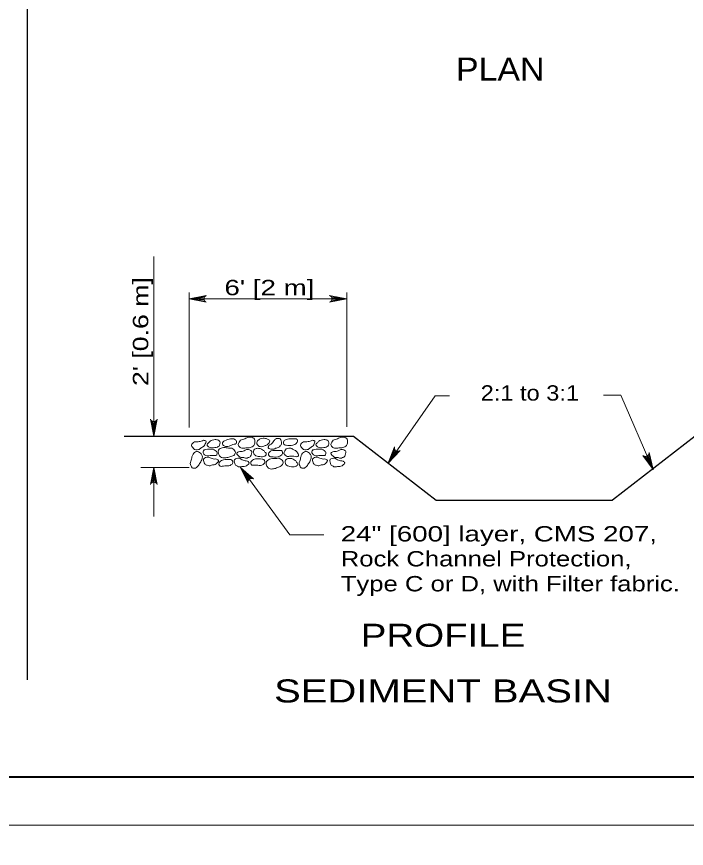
# Model space of a CAD drawing. Extents: x 1043.1 to 1101.1, y 672.4 to 716.4.
# Drawn here: x 1065.65 to 1072.63, y 694.15 to 702.82 of the extents above; entities that cross this region are included whole.
import ezdxf
from ezdxf.enums import TextEntityAlignment as Align

# ---------------------------------------------------------------- set-up
doc = ezdxf.new("R2010")
doc.units = 0
doc.header["$LTSCALE"] = 0.064
doc.linetypes.add('LONG_DASHED', pattern=[7.5, 6, -1.5])
doc.layers.add('1', color=7, linetype='Continuous', lineweight=13)

msp = doc.modelspace()

# ---------------------------------------------------------------- linework, layer by layer
at = {"layer": '1', "lineweight": 25}
for p, q in [((1065.75725, 705.79967), (1065.75725, 695.90875)), ((1066.76875, 698.44833), (1069.16058, 698.44833)), ((1072.72475, 698.44833), (1071.86283, 697.78133))]:
    msp.add_line(p, q, dxfattribs=at)
at = {"layer": '1'}
for p, q in [((1067.07925, 700.32167), (1067.07925, 698.44833)), ((1067.44858, 699.94717), (1067.44858, 698.53933)), ((1069.09117, 699.94717), (1069.09117, 698.54667)), ((1067.61175, 699.90575), (1067.44858, 699.88083)), ((1067.60558, 699.89533), (1067.44858, 699.88083)), ((1069.09117, 699.88083), (1067.44858, 699.88083)), ((1067.60275, 699.88083), (1067.44858, 699.88083)), ((1067.60442, 699.86942), (1067.44858, 699.88083)), ((1067.60983, 699.85825), (1067.44858, 699.88083)), ((1067.59725, 699.88083), (1067.45083, 699.88083)), ((1068.928, 699.85592), (1069.09117, 699.88083)), ((1068.92992, 699.90342), (1069.09117, 699.88083)), ((1068.93417, 699.86633), (1069.09117, 699.88083)), ((1068.93533, 699.89225), (1069.09117, 699.88083)), ((1068.937, 699.88083), (1069.09117, 699.88083)), ((1068.9425, 699.88083), (1069.08892, 699.88083)), ((1067.05433, 698.6115), (1067.07925, 698.44833)), ((1067.06475, 698.60533), (1067.07925, 698.44833)), ((1067.10183, 698.60958), (1067.07925, 698.44833)), ((1067.09067, 698.60417), (1067.07925, 698.44833)), ((1067.07925, 698.6025), (1067.07925, 698.44833)), ((1067.07925, 698.597), (1067.07925, 698.45058)), ((1069.58933, 698.31933), (1069.52217, 698.1685)), ((1069.59483, 698.30842), (1069.52217, 698.1685)), ((1069.60542, 698.29825), (1069.52217, 698.1685)), ((1069.61592, 698.2935), (1069.52217, 698.1685)), ((1069.62825, 698.292), (1069.52217, 698.1685)), ((1069.6025, 698.29358), (1069.52333, 698.17042)), ((1072.196, 698.24008), (1072.28517, 698.10117)), ((1072.208, 698.23867), (1072.28517, 698.10117)), ((1072.22242, 698.24192), (1072.28517, 698.10117)), ((1072.22467, 698.237), (1072.28433, 698.10317)), ((1072.23217, 698.24808), (1072.28517, 698.10117)), ((1072.24017, 698.25767), (1072.28517, 698.10117)), ((1067.44858, 698.12408), (1066.94558, 698.12408)), ((1067.05667, 697.96283), (1067.07925, 698.12408)), ((1067.06783, 697.96825), (1067.07925, 698.12408)), ((1067.07925, 697.61308), (1067.07925, 698.12408)), ((1067.07925, 697.96992), (1067.07925, 698.12408)), ((1067.09375, 697.96708), (1067.07925, 698.12408)), ((1067.10417, 697.96092), (1067.07925, 698.12408)), ((1067.07925, 697.97542), (1067.07925, 698.12183)), ((1068.07558, 698.00092), (1067.98217, 698.1235)), ((1068.08883, 698.00742), (1067.98217, 698.1235)), ((1068.10092, 698.00883), (1067.98217, 698.1235)), ((1068.06775, 697.99258), (1067.98217, 698.1235)), ((1068.06208, 697.98158), (1067.98217, 698.1235)), ((1068.07225, 698.00525), (1067.98358, 698.12175))]:
    msp.add_line(p, q, dxfattribs=at)
at = {"layer": '1', "linetype": 'LONG_DASHED'}
for points in [[(1043.14425, 694.39508), (1077.14425, 694.39508), (1077.14425, 716.39508), (1043.14425, 716.39508)], [(1043.14425, 672.39508), (1077.14425, 672.39508), (1077.14425, 694.39508), (1043.14425, 694.39508)]]:
    msp.add_lwpolyline(points, close=True, dxfattribs=at)
at = {"layer": '1', "lineweight": 25}
for points in [[(1076.64425, 694.89508), (1045.14425, 694.89508), (1045.14425, 715.89508)], [(1069.16058, 698.44833), (1070.0225, 697.78133), (1071.86283, 697.78133)]]:
    msp.add_lwpolyline(points, dxfattribs=at)
at = {"layer": '1', "lineweight": 40}
msp.add_lwpolyline([(1045.14425, 715.89508), (1076.64425, 715.89508), (1076.64425, 694.89508), (1045.14425, 694.89508)], close=True, dxfattribs=at)
msp.add_lwpolyline([(1076.64425, 694.89508), (1045.14425, 694.89508), (1045.14425, 715.89508)], dxfattribs=at)
at = {"layer": '1'}
for points in [[(1067.62675, 699.91642), (1067.44858, 699.88083), (1067.62675, 699.84525)], [(1068.91308, 699.84525), (1069.09117, 699.88083), (1068.91308, 699.91642)], [(1070.16233, 698.871), (1070.013, 698.871), (1069.52217, 698.1685)], [(1071.7705, 698.87883), (1071.95125, 698.87883), (1072.28742, 698.10025)], [(1067.04358, 698.6265), (1067.07925, 698.44833), (1067.11492, 698.6265)], [(1069.58842, 698.33767), (1069.52217, 698.1685), (1069.64833, 698.29917)], [(1072.18008, 698.24942), (1072.28517, 698.10117), (1072.24525, 698.27842)], [(1067.11492, 697.946), (1067.07925, 698.12408), (1067.04358, 697.946)], [(1068.11833, 698.00342), (1067.98217, 698.1235), (1068.06183, 697.96033)], [(1068.85283, 697.42283), (1068.49617, 697.42283), (1067.9835, 698.12525)]]:
    msp.add_lwpolyline(points, dxfattribs=at)
for centre, start, end in [((1067.64109, 699.88079), 112.08605, 247.91218), ((1068.89866, 699.88087), 292.08605, 67.91218), ((1067.07929, 698.64084), 202.08605, 337.91218), ((1069.62619, 698.33048), 169.38859, 305.21471), ((1072.20684, 698.27705), 226.10574, 1.93187), ((1067.07921, 697.93158), 22.08605, 157.91218), ((1068.09888, 697.97042), 59.38859, 195.21471)]:
    msp.add_arc(centre, 0.03845, start, end, dxfattribs=at)
for points in [[(1067.61217, 698.35908), (1067.62058, 698.37867), (1067.62142, 698.4), (1067.61167, 698.40425), (1067.59767, 698.40683), (1067.57408, 698.39667), (1067.55275, 698.39308), (1067.52908, 698.39117), (1067.51242, 698.39242), (1067.49458, 698.38508), (1067.47683, 698.36533), (1067.472, 698.35133), (1067.48542, 698.331), (1067.50392, 698.31175), (1067.53267, 698.30875), (1067.55375, 698.312), (1067.58092, 698.333), (1067.59675, 698.34133), (1067.61217, 698.35908)], [(1067.75942, 698.34675), (1067.74183, 698.3355), (1067.71583, 698.33025), (1067.68492, 698.32925), (1067.65742, 698.33492), (1067.64275, 698.34642), (1067.63508, 698.36208), (1067.64475, 698.37542), (1067.66583, 698.397), (1067.68842, 698.40875), (1067.71908, 698.41433), (1067.75242, 698.40708), (1067.76683, 698.39308), (1067.76925, 698.3695), (1067.75942, 698.34675)], [(1067.86525, 698.34683), (1067.836, 698.34242), (1067.80617, 698.3525), (1067.79608, 698.37092), (1067.8015, 698.39092), (1067.8165, 698.40058), (1067.88, 698.42275), (1067.92492, 698.416), (1067.942, 698.39292), (1067.93633, 698.37225), (1067.91858, 698.3655), (1067.86525, 698.34683)], [(1068.10392, 698.33933), (1068.12225, 698.35392), (1068.13367, 698.38508), (1068.12192, 698.42767), (1068.07825, 698.4405), (1068.04892, 698.43333), (1068.00558, 698.41458), (1067.98358, 698.40683), (1067.969, 698.38708), (1067.95992, 698.36233), (1067.97833, 698.3325), (1067.99775, 698.326), (1068.04058, 698.32683), (1068.08492, 698.33225), (1068.10392, 698.33933)], [(1068.17875, 698.3435), (1068.1995, 698.34033), (1068.22533, 698.346), (1068.25408, 698.35758), (1068.27683, 698.37383), (1068.28558, 698.39042), (1068.28642, 698.40775), (1068.27208, 698.416), (1068.24408, 698.42717), (1068.21867, 698.42892), (1068.18842, 698.42142), (1068.16083, 698.4015), (1068.15325, 698.38267), (1068.16067, 698.36042), (1068.17875, 698.3435)], [(1068.31025, 698.31317), (1068.2895, 698.31792), (1068.27142, 698.32958), (1068.27383, 698.34008), (1068.27975, 698.35308), (1068.30175, 698.36633), (1068.31717, 698.3815), (1068.33225, 698.39975), (1068.34117, 698.414), (1068.35733, 698.42408), (1068.38383, 698.42717), (1068.398, 698.42283), (1068.40683, 698.40017), (1068.41167, 698.37408), (1068.39725, 698.34867), (1068.3825, 698.33358), (1068.34967, 698.32367), (1068.33367, 698.31558), (1068.31025, 698.31317)], [(1068.489, 698.42192), (1068.46008, 698.41642), (1068.43517, 698.39692), (1068.43175, 698.37617), (1068.44375, 698.35925), (1068.46092, 698.35492), (1068.528, 698.355), (1068.56817, 698.37617), (1068.57683, 698.40358), (1068.56475, 698.42125), (1068.54567, 698.42192), (1068.489, 698.42192)], [(1068.74767, 698.35908), (1068.75608, 698.37867), (1068.75692, 698.4), (1068.74717, 698.40425), (1068.73317, 698.40683), (1068.70958, 698.39667), (1068.68825, 698.39308), (1068.66458, 698.39117), (1068.64792, 698.39242), (1068.63008, 698.38508), (1068.61233, 698.36533), (1068.6075, 698.35133), (1068.62092, 698.331), (1068.63942, 698.31175), (1068.66817, 698.30875), (1068.68925, 698.312), (1068.71642, 698.333), (1068.73225, 698.34133), (1068.74767, 698.35908)], [(1068.89492, 698.34675), (1068.87733, 698.3355), (1068.85133, 698.33025), (1068.82042, 698.32925), (1068.79292, 698.33492), (1068.77825, 698.34642), (1068.77058, 698.36208), (1068.78025, 698.37542), (1068.80133, 698.397), (1068.82392, 698.40875), (1068.85458, 698.41433), (1068.88792, 698.40708), (1068.90233, 698.39308), (1068.90475, 698.3695), (1068.89492, 698.34675)], [(1069.07075, 698.33933), (1069.08908, 698.35392), (1069.1005, 698.38508), (1069.08875, 698.42767), (1069.04508, 698.4405), (1069.01575, 698.43333), (1068.97242, 698.41458), (1068.95042, 698.40683), (1068.93583, 698.38708), (1068.92675, 698.36233), (1068.94517, 698.3325), (1068.96458, 698.326), (1069.00742, 698.32683), (1069.05175, 698.33225), (1069.07075, 698.33933)], [(1067.58483, 698.2215), (1067.58425, 698.24492), (1067.56625, 698.27292), (1067.52508, 698.28908), (1067.48875, 698.26208), (1067.47692, 698.23433), (1067.4655, 698.18833), (1067.45858, 698.16592), (1067.46558, 698.14242), (1067.47983, 698.12042), (1067.51467, 698.11717), (1067.5315, 698.12875), (1067.55683, 698.1635), (1067.57917, 698.20217), (1067.58483, 698.2215)], [(1067.65217, 698.24533), (1067.62292, 698.24942), (1067.59708, 698.26767), (1067.59275, 698.28825), (1067.60375, 698.30583), (1067.62075, 698.31075), (1067.68792, 698.31392), (1067.72892, 698.2945), (1067.73892, 698.26767), (1067.7275, 698.2495), (1067.70858, 698.248), (1067.65217, 698.24533)], [(1067.79808, 698.22483), (1067.77633, 698.23333), (1067.75608, 698.25967), (1067.75458, 698.30392), (1067.79233, 698.329), (1067.82267, 698.33092), (1067.86967, 698.326), (1067.89308, 698.32492), (1067.91283, 698.3105), (1067.92867, 698.28975), (1067.92, 698.25567), (1067.90342, 698.24367), (1067.86242, 698.23167), (1067.81842, 698.22367), (1067.79808, 698.22483)], [(1067.96958, 698.23858), (1067.95375, 698.253), (1067.94408, 698.272), (1067.95117, 698.27983), (1067.96283, 698.28825), (1067.9885, 698.28883), (1068.00942, 698.29433), (1068.03158, 698.30267), (1068.04633, 698.31075), (1068.0655, 698.31158), (1068.09, 698.301), (1068.10008, 698.29025), (1068.09642, 698.26625), (1068.08767, 698.24092), (1068.06292, 698.22608), (1068.04242, 698.22033), (1068.009, 698.228), (1067.99108, 698.229), (1067.96958, 698.23858)], [(1068.12692, 698.25883), (1068.14367, 698.24608), (1068.169, 698.23875), (1068.19983, 698.23533), (1068.22775, 698.23883), (1068.24325, 698.24917), (1068.25225, 698.26425), (1068.24358, 698.27817), (1068.22425, 698.30133), (1068.20258, 698.31508), (1068.17242, 698.32283), (1068.13875, 698.31833), (1068.12317, 698.3055), (1068.11892, 698.28225), (1068.12692, 698.25883)], [(1068.33375, 698.30125), (1068.30467, 698.29575), (1068.27983, 698.27633), (1068.27633, 698.25558), (1068.28833, 698.23858), (1068.3055, 698.23442), (1068.37258, 698.2345), (1068.41283, 698.25558), (1068.42158, 698.283), (1068.40933, 698.30067), (1068.39042, 698.30125), (1068.33375, 698.30125)], [(1068.57375, 698.28417), (1068.5845, 698.26575), (1068.58808, 698.24475), (1068.57883, 698.23917), (1068.56525, 698.23483), (1068.54058, 698.24183), (1068.51908, 698.24292), (1068.49533, 698.24158), (1068.47892, 698.23833), (1068.4605, 698.24317), (1068.44042, 698.26067), (1068.43375, 698.27392), (1068.4445, 698.29567), (1068.46033, 698.31717), (1068.4885, 698.32392), (1068.50967, 698.32333), (1068.53933, 698.306), (1068.55608, 698.29975), (1068.57375, 698.28417)], [(1068.72033, 698.2215), (1068.71975, 698.24492), (1068.70175, 698.27292), (1068.66058, 698.28908), (1068.62425, 698.26208), (1068.61242, 698.23433), (1068.601, 698.18833), (1068.59408, 698.16592), (1068.60108, 698.14242), (1068.61533, 698.12042), (1068.65017, 698.11717), (1068.667, 698.12875), (1068.69233, 698.1635), (1068.71467, 698.20217), (1068.72033, 698.2215)], [(1068.78767, 698.24533), (1068.75842, 698.24942), (1068.73258, 698.26767), (1068.72825, 698.28825), (1068.73925, 698.30583), (1068.75625, 698.31075), (1068.82342, 698.31392), (1068.86442, 698.2945), (1068.87442, 698.26767), (1068.863, 698.2495), (1068.84408, 698.248), (1068.78767, 698.24533)], [(1068.95217, 698.23858), (1068.93633, 698.253), (1068.92667, 698.272), (1068.93375, 698.27983), (1068.94542, 698.28825), (1068.97108, 698.28883), (1068.992, 698.29433), (1069.01417, 698.30267), (1069.02892, 698.31075), (1069.04808, 698.31158), (1069.07258, 698.301), (1069.08267, 698.29025), (1069.079, 698.26625), (1069.07025, 698.24092), (1069.0455, 698.22608), (1069.025, 698.22033), (1068.99158, 698.228), (1068.97367, 698.229), (1068.95217, 698.23858)], [(1067.72942, 698.16142), (1067.74467, 698.17633), (1067.75383, 698.19558), (1067.7465, 698.20325), (1067.73467, 698.21125), (1067.70908, 698.21108), (1067.68792, 698.216), (1067.6655, 698.22358), (1067.65058, 698.231), (1067.63133, 698.23133), (1067.60733, 698.22008), (1067.59742, 698.209), (1067.60175, 698.18508), (1067.61125, 698.16017), (1067.63658, 698.14617), (1067.65725, 698.141), (1067.69042, 698.14958), (1067.70817, 698.15108), (1067.72942, 698.16142)], [(1067.84725, 698.139), (1067.87617, 698.14575), (1067.90008, 698.16633), (1067.90258, 698.18725), (1067.89008, 698.20375), (1067.87258, 698.20708), (1067.80525, 698.20392), (1067.76625, 698.181), (1067.75883, 698.15325), (1067.77175, 698.13625), (1067.79075, 698.13642), (1067.84725, 698.139)], [(1068.04525, 698.14108), (1068.06217, 698.15417), (1068.07342, 698.17217), (1068.067, 698.18067), (1068.05608, 698.18992), (1068.0305, 698.19258), (1068.01017, 698.19975), (1067.98858, 698.20975), (1067.97458, 698.21892), (1067.9555, 698.22133), (1067.93033, 698.21275), (1067.91917, 698.20283), (1067.921, 698.17858), (1067.92783, 698.15283), (1067.95133, 698.13592), (1067.97125, 698.12858), (1068.00525, 698.13358), (1068.02308, 698.13317), (1068.04525, 698.14108)], [(1068.17708, 698.14458), (1068.20625, 698.14883), (1068.232, 698.16725), (1068.23617, 698.18792), (1068.22508, 698.20533), (1068.20808, 698.21017), (1068.14075, 698.21275), (1068.09992, 698.19325), (1068.09008, 698.16625), (1068.10158, 698.14817), (1068.12058, 698.14683), (1068.17708, 698.14458)], [(1068.30533, 698.10725), (1068.28267, 698.11275), (1068.25908, 698.13625), (1068.25192, 698.17975), (1068.286, 698.20975), (1068.31558, 698.21567), (1068.36283, 698.217), (1068.38625, 698.21917), (1068.40767, 698.2075), (1068.42625, 698.18892), (1068.42208, 698.15392), (1068.40725, 698.13992), (1068.36808, 698.12258), (1068.32567, 698.10875), (1068.30533, 698.10725)], [(1068.45658, 698.15417), (1068.47333, 698.1415), (1068.49867, 698.13408), (1068.5295, 698.13067), (1068.55725, 698.13408), (1068.57283, 698.14442), (1068.58175, 698.15942), (1068.57308, 698.17342), (1068.55375, 698.19667), (1068.53217, 698.21033), (1068.50208, 698.21808), (1068.46842, 698.21358), (1068.45283, 698.20075), (1068.44858, 698.17758), (1068.45658, 698.15417)], [(1068.86492, 698.16142), (1068.88017, 698.17633), (1068.88933, 698.19558), (1068.882, 698.20325), (1068.87017, 698.21125), (1068.84458, 698.21108), (1068.82342, 698.216), (1068.801, 698.22358), (1068.78608, 698.231), (1068.76683, 698.23133), (1068.74283, 698.22008), (1068.73292, 698.209), (1068.73725, 698.18508), (1068.74675, 698.16017), (1068.77208, 698.14617), (1068.79275, 698.141), (1068.82592, 698.14958), (1068.84367, 698.15108), (1068.86492, 698.16142)], [(1069.04183, 698.14108), (1069.05875, 698.15417), (1069.07, 698.17217), (1069.06358, 698.18067), (1069.05267, 698.18992), (1069.02708, 698.19258), (1069.00675, 698.19975), (1068.98517, 698.20975), (1068.97117, 698.21892), (1068.95208, 698.22133), (1068.92692, 698.21275), (1068.91575, 698.20283), (1068.91758, 698.17858), (1068.92442, 698.15283), (1068.94792, 698.13592), (1068.96783, 698.12858), (1069.00183, 698.13358), (1069.01967, 698.13317), (1069.04183, 698.14108)]]:
    msp.add_spline(points, degree=3, dxfattribs=at)

# ---------------------------------------------------------------- texts
for s, height, width, p in [('PLAN', 0.24, 1.1, (1070.69183, 702.15592)), ("6' [2 m]", 0.16, 1.35, (1068.28488, 699.91908)), ('2:1 to 3:1', 0.16, 1.15, (1071.00071, 698.82042)), ('PROFILE', 0.24, 1.25, (1070.0955, 696.25442)), ('SEDIMENT BASIN', 0.24, 1.3, (1070.0955, 695.67417))]:
    msp.add_text(s, height=height, dxfattribs=dict(at, width=width)).set_placement(p, align=Align.CENTER)
at = {"layer": '1', "width": 1.3}
msp.add_text("2' [0.6 m]", height=0.16, rotation=90, dxfattribs=at).set_placement((1067.02108, 699.54029), align=Align.CENTER)
at = {"layer": '1'}
for s, width, p in [('24" [600] layer, CMS 207,', 1.35, (1069.02892, 697.352)), ('Rock Channel Protection,', 1.25, (1069.02892, 697.092)), ('Type C or D, with Filter fabric.', 1.25, (1069.02892, 696.832))]:
    msp.add_text(s, height=0.16, dxfattribs=dict(at, width=width)).set_placement(p)

doc.saveas('drawing.dxf')
